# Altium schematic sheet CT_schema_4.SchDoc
size 221 x 258 mm
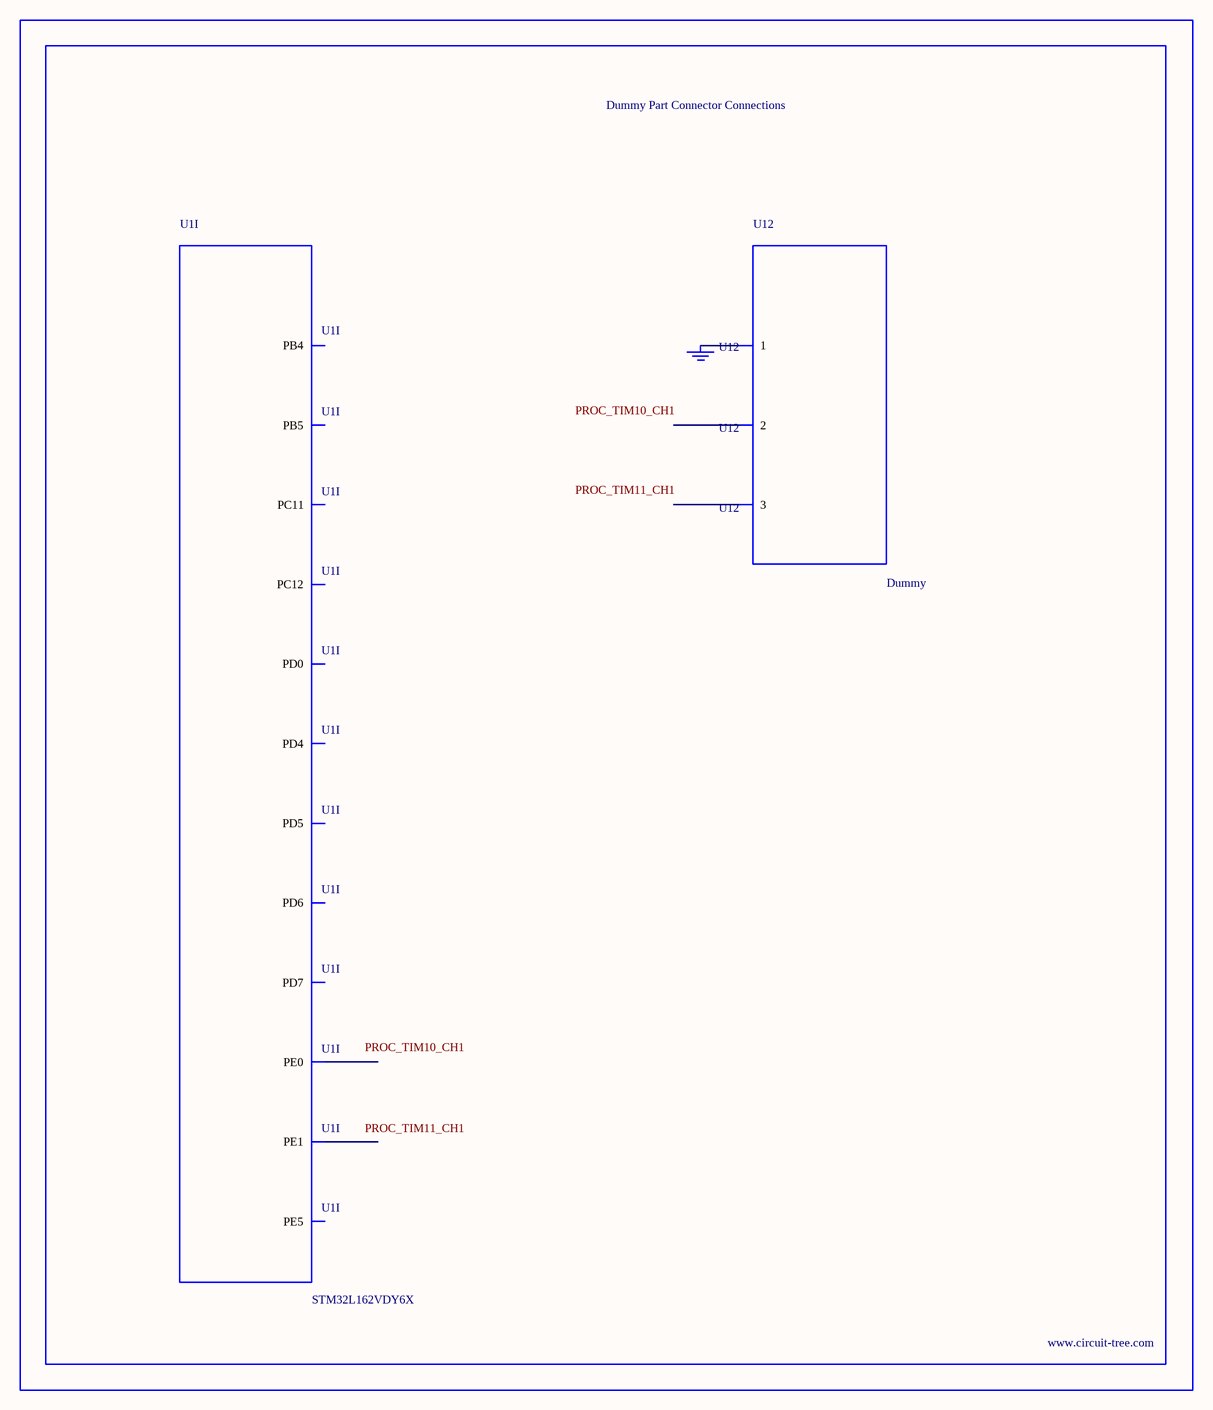
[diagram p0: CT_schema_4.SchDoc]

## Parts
BORDER3  (no value)
GND_INSTANCE_3_0  (no value)
U1  STM32L162VDY6X  [WLCSP104]  (part I of 9)
U12  Dummy  [DUMMY_PACKAGE_121]

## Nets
NetGND_INSTANCE_3_0_0: GND_INSTANCE_3_0.0(GND) U12.1

Not connected (* = marked no-connect by the designer): U1 A2(PD0) A3(PD4) A4(PD7) A5(PB4) A6(PB5) A8(PE1) B2(PC12) B3(PD5) B4(PD6) B7(PE0) B9(PE5) C2(PC11); U12 2 3

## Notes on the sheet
- Labels drawn without touching a wire or pin: PROC_TIM10_CH1, PROC_TIM11_CH1

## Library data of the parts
BORDER3 = BORDER_PAGE3
GND_INSTANCE_3_0 = GND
